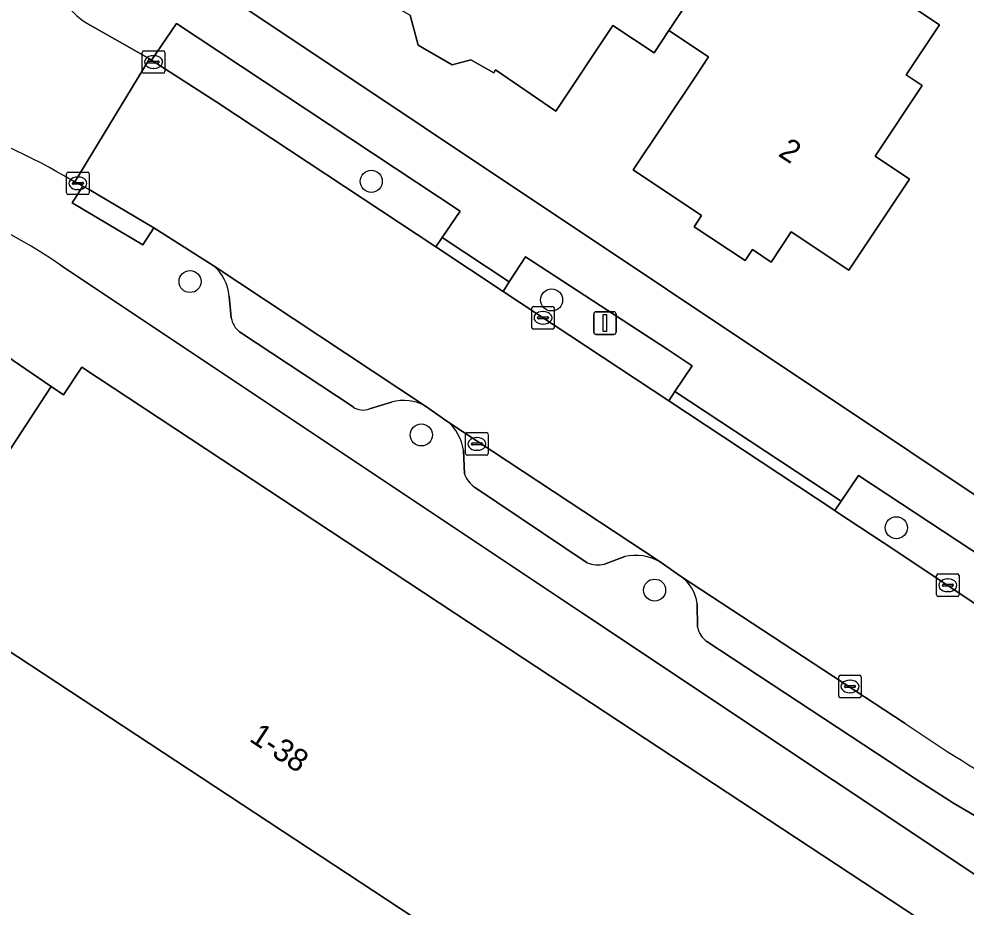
# Model space of a CAD drawing. Extents: x 161772 to 163126, y 383092 to 383917.
# Drawn here: x 162367.96 to 162409.94, y 383486.96 to 383526.35 of the extents above; entities that cross this region are included whole.
import ezdxf

# ---------------------------------------------------------------- set-up
doc = ezdxf.new("R2010")
doc.units = 0
for name, color, linetype in [('IMGEO_Boom', 7, 'Continuous'), ('IMGEO_Erf', 7, 'Continuous'), ('IMGEO_Groenvoorziening', 7, 'Continuous'), ('IMGEO_Kolk', 7, 'Continuous'), ('IMGEO_Lichtmast', 7, 'Continuous'), ('IMGEO_Pand', 7, 'Continuous'), ('IMGEO_Pand_nummerreeks', 7, 'Continuous'), ('IMGEO_Parkeervlak_open', 7, 'Continuous'), ('IMGEO_Rijbaan_lokaal_gesloten', 7, 'Continuous'), ('IMGEO_Rijbaan_lokaal_open', 7, 'Continuous'), ('IMGEO_Voetpad_open', 7, 'Continuous')]:
    doc.layers.add(name, color=color, linetype=linetype)

msp = doc.modelspace()

# ---------------------------------------------------------------- linework, layer by layer
at = {"layer": 'IMGEO_Boom'}
for centre in [(162383.578, 383519.145), (162375.545, 383514.701), (162391.571, 383513.885), (162385.797, 383507.897), (162406.85, 383503.782), (162396.136, 383501.014)]:
    msp.add_circle(centre, 0.489, dxfattribs=at)
at = {"layer": 'IMGEO_Erf'}
for points in [[(162462.704, 383536.779), (162483.744, 383554.98), (162500, 383574.599), (162526.947, 383607.122), (162543.804, 383623.317), (162548.918, 383628.126), (162539.791, 383641.093), (162527.133, 383641.683), (162527.105, 383641.456), (162500, 383642.583), (162442.25, 383644.984), (162375.184, 383528.714), (162418.191, 383500), (162425.357, 383495.215)], [(162403.897, 383529.321), (162408.758, 383526.086), (162407.282, 383523.868), (162407.993, 383523.394), (162405.908, 383520.26), (162407.433, 383519.245), (162404.746, 383515.207), (162402.195, 383516.905), (162401.305, 383515.567), (162400.476, 383516.119), (162400.148, 383515.627), (162397.885, 383517.133), (162398.22, 383517.636), (162395.189, 383519.652), (162397.959, 383523.815), (162398.523, 383524.663), (162396.772, 383525.831), (162396.111, 383524.841), (162394.289, 383526.056), (162391.754, 383522.254), (162389.089, 383524.092), (162389.009, 383523.954), (162387.994, 383524.54), (162387.16, 383524.317), (162385.651, 383525.187), (162385.295, 383526.511)], [(162415.606, 383482.867), (162415.154, 383485.181), (162392.934, 383500), (162369.796, 383515.431)]]:
    msp.add_lwpolyline(points, dxfattribs=at)
msp.add_lwpolyline([(162351.52, 383514.81), (162359.75, 383515.42), (162359.94, 383512.6), (162365.41, 383510.83), (162366.29, 383512.16), (162369.386, 383510.049), (162369.936, 383509.674), (162370.747, 383510.9), (162387.282, 383500), (162408.441, 383486.052), (162399.683, 383472.842), (162389.098, 383463.766), (162387.275, 383465.894), (162382.993, 383470.891), (162381.153, 383473.039), (162391.903, 383482.254), (162364.962, 383500), (162363.969, 383500.654), (162365.459, 383502.906), (162364.939, 383503.25), (162362.306, 383504.993), (162356.802, 383504.584), (162356.592, 383507.406), (162352.094, 383507.072)], close=True, dxfattribs=at)
msp.add_arc((162355.644, 383494.899), 24.937, 55.4234, 93.0188, dxfattribs=at)
at = {"layer": 'IMGEO_Groenvoorziening'}
for points in [[(162373.834, 383524.516), (162376.728, 383522.659), (162386.44, 383516.235), (162386.721, 383516.648), (162387.516, 383517.815), (162374.942, 383526.139)], [(162389.694, 383514.682), (162389.421, 383514.263), (162396.76, 383509.409), (162397.037, 383509.82), (162397.802, 383510.956), (162396.699, 383511.708), (162390.42, 383515.798)]]:
    msp.add_lwpolyline(points, close=True, dxfattribs=at)
for points in [[(162418.384, 383495.476), (162419.246, 383496.818), (162417.08, 383498.245), (162405.174, 383506.099), (162404.404, 383504.955)], [(162404.404, 383504.955), (162404.125, 383504.54), (162404.195, 383504.494), (162406.79, 383502.794), (162410.958, 383500), (162415.501, 383497.08)]]:
    msp.add_lwpolyline(points, dxfattribs=at)
at = {"layer": 'IMGEO_Kolk'}
for p, q in [((162373.427, 383524.01), (162373.427, 383524.862)), ((162373.502, 383524.936), (162374.354, 383524.936)), ((162373.915, 383524.716), (162373.94, 383524.716)), ((162374.428, 383524.862), (162374.428, 383524.01)), ((162373.686, 383524.43), (162373.686, 383524.442)), ((162374.124, 383524.393), (162373.726, 383524.393)), ((162373.729, 383524.479), (162374.127, 383524.479)), ((162373.938, 383524.156), (162373.913, 383524.156)), ((162374.17, 383524.442), (162374.17, 383524.43)), ((162374.354, 383523.936), (162373.502, 383523.936)), ((162370.147, 383519.556), (162370.999, 383519.556)), ((162370.072, 383518.63), (162370.072, 383519.482)), ((162370.374, 383519.099), (162370.772, 383519.099)), ((162370.56, 383519.336), (162370.585, 383519.336)), ((162371.073, 383519.482), (162371.073, 383518.63)), ((162370.331, 383519.05), (162370.331, 383519.062)), ((162370.769, 383519.013), (162370.371, 383519.013)), ((162370.583, 383518.776), (162370.558, 383518.776)), ((162370.815, 383519.062), (162370.815, 383519.05)), ((162370.999, 383518.556), (162370.147, 383518.556)), ((162390.69, 383512.667), (162390.69, 383513.519)), ((162390.765, 383513.593), (162391.617, 383513.593)), ((162391.178, 383513.373), (162391.203, 383513.373)), ((162391.691, 383513.519), (162391.691, 383512.667)), ((162390.949, 383513.087), (162390.949, 383513.099)), ((162391.387, 383513.05), (162390.989, 383513.05)), ((162390.992, 383513.136), (162391.39, 383513.136)), ((162391.201, 383512.813), (162391.176, 383512.813)), ((162391.433, 383513.099), (162391.433, 383513.087)), ((162391.617, 383512.593), (162390.765, 383512.593)), ((162387.758, 383507.072), (162387.758, 383507.924)), ((162387.833, 383507.998), (162388.685, 383507.998)), ((162388.246, 383507.778), (162388.271, 383507.778)), ((162388.759, 383507.924), (162388.759, 383507.072)), ((162388.017, 383507.492), (162388.017, 383507.504)), ((162388.455, 383507.455), (162388.057, 383507.455)), ((162388.06, 383507.541), (162388.458, 383507.541)), ((162388.501, 383507.504), (162388.501, 383507.492)), ((162388.685, 383506.998), (162387.833, 383506.998)), ((162388.269, 383507.218), (162388.244, 383507.218)), ((162408.633, 383500.804), (162408.633, 383501.656)), ((162408.708, 383501.73), (162409.56, 383501.73)), ((162409.121, 383501.51), (162409.146, 383501.51)), ((162409.634, 383501.656), (162409.634, 383500.804)), ((162408.892, 383501.224), (162408.892, 383501.236)), ((162409.33, 383501.187), (162408.932, 383501.187)), ((162408.935, 383501.273), (162409.333, 383501.273)), ((162409.376, 383501.236), (162409.376, 383501.224)), ((162409.56, 383500.73), (162408.708, 383500.73)), ((162409.144, 383500.95), (162409.119, 383500.95)), ((162404.297, 383496.315), (162404.297, 383497.167)), ((162404.372, 383497.241), (162405.224, 383497.241)), ((162404.785, 383497.021), (162404.81, 383497.021)), ((162405.298, 383497.167), (162405.298, 383496.315)), ((162404.556, 383496.735), (162404.556, 383496.747)), ((162404.994, 383496.698), (162404.596, 383496.698)), ((162404.599, 383496.784), (162404.997, 383496.784)), ((162404.808, 383496.461), (162404.783, 383496.461)), ((162405.04, 383496.747), (162405.04, 383496.735)), ((162405.224, 383496.241), (162404.372, 383496.241))]:
    msp.add_line(p, q, dxfattribs=at)
for points in [[(162373.427, 383524.01), (162373.427, 383524.862)], [(162373.502, 383524.936), (162374.354, 383524.936)], [(162374.428, 383524.862), (162374.428, 383524.01)], [(162374.354, 383523.936), (162373.502, 383523.936)], [(162370.147, 383519.556), (162370.999, 383519.556)], [(162370.072, 383518.63), (162370.072, 383519.482)], [(162371.073, 383519.482), (162371.073, 383518.63)], [(162370.999, 383518.556), (162370.147, 383518.556)], [(162390.69, 383512.667), (162390.69, 383513.519)], [(162390.765, 383513.593), (162391.617, 383513.593)], [(162391.691, 383513.519), (162391.691, 383512.667)], [(162391.617, 383512.593), (162390.765, 383512.593)], [(162387.758, 383507.072), (162387.758, 383507.924)], [(162387.833, 383507.998), (162388.685, 383507.998)], [(162388.759, 383507.924), (162388.759, 383507.072)], [(162388.685, 383506.998), (162387.833, 383506.998)], [(162408.633, 383500.804), (162408.633, 383501.656)], [(162408.708, 383501.73), (162409.56, 383501.73)], [(162409.634, 383501.656), (162409.634, 383500.804)], [(162409.56, 383500.73), (162408.708, 383500.73)], [(162404.297, 383496.315), (162404.297, 383497.167)], [(162404.372, 383497.241), (162405.224, 383497.241)], [(162405.298, 383497.167), (162405.298, 383496.315)], [(162405.224, 383496.241), (162404.372, 383496.241)]]:
    msp.add_lwpolyline(points, dxfattribs=at)
for centre, radius, start, end in [((162373.504, 383524.86), 0.0765, 91.552, 178.448), ((162373.504, 383524.86), 0.0765, 91.552, 178.448), ((162374.352, 383524.86), 0.0765, 1.552, 88.448), ((162374.352, 383524.86), 0.0765, 1.552, 88.448), ((162373.726, 383524.439), 0.0403, 85.8775, 175.7526), ((162373.723, 383524.429), 0.0366, 178.938, 274.7102), ((162374.127, 383524.436), 0.043, 264.8664, 352.4533), ((162374.131, 383524.441), 0.0386, 1.7309, 96.639), ((162373.504, 383524.012), 0.0765, 181.552, 268.448), ((162373.504, 383524.012), 0.0765, 181.552, 268.448), ((162374.352, 383524.012), 0.0765, 271.552, 358.448), ((162374.352, 383524.012), 0.0765, 271.552, 358.448), ((162370.149, 383519.48), 0.0765, 91.552, 178.448), ((162370.149, 383519.48), 0.0765, 91.552, 178.448), ((162370.997, 383519.48), 0.0765, 1.552, 88.448), ((162370.997, 383519.48), 0.0765, 1.552, 88.448), ((162370.371, 383519.059), 0.0403, 85.8775, 175.7526), ((162370.776, 383519.061), 0.0386, 1.7309, 96.639), ((162370.368, 383519.049), 0.0366, 178.938, 274.7102), ((162370.772, 383519.056), 0.043, 264.8664, 352.4533), ((162370.149, 383518.632), 0.0765, 181.552, 268.448), ((162370.149, 383518.632), 0.0765, 181.552, 268.448), ((162370.997, 383518.632), 0.0765, 271.552, 358.448), ((162370.997, 383518.632), 0.0765, 271.552, 358.448), ((162390.767, 383513.517), 0.0765, 91.552, 178.448), ((162390.767, 383513.517), 0.0765, 91.552, 178.448), ((162391.615, 383513.517), 0.0765, 1.552, 88.448), ((162391.615, 383513.517), 0.0765, 1.552, 88.448), ((162390.989, 383513.096), 0.0403, 85.8775, 175.7526), ((162390.986, 383513.086), 0.0366, 178.938, 274.7102), ((162391.39, 383513.093), 0.043, 264.8664, 352.4533), ((162391.394, 383513.098), 0.0386, 1.7309, 96.639), ((162390.767, 383512.669), 0.0765, 181.552, 268.448), ((162390.767, 383512.669), 0.0765, 181.552, 268.448), ((162391.615, 383512.669), 0.0765, 271.552, 358.448), ((162391.615, 383512.669), 0.0765, 271.552, 358.448), ((162387.835, 383507.922), 0.0765, 91.552, 178.448), ((162387.835, 383507.922), 0.0765, 91.552, 178.448), ((162388.683, 383507.922), 0.0765, 1.552, 88.448), ((162388.683, 383507.922), 0.0765, 1.552, 88.448), ((162388.057, 383507.501), 0.0403, 85.8775, 175.7526), ((162388.054, 383507.491), 0.0366, 178.938, 274.7102), ((162388.458, 383507.498), 0.043, 264.8664, 352.4533), ((162388.462, 383507.503), 0.0386, 1.7309, 96.639), ((162387.835, 383507.074), 0.0765, 181.552, 268.448), ((162387.835, 383507.074), 0.0765, 181.552, 268.448), ((162388.683, 383507.074), 0.0765, 271.552, 358.448), ((162388.683, 383507.074), 0.0765, 271.552, 358.448), ((162408.71, 383501.654), 0.0765, 91.552, 178.448), ((162408.71, 383501.654), 0.0765, 91.552, 178.448), ((162409.558, 383501.654), 0.0765, 1.552, 88.448), ((162409.558, 383501.654), 0.0765, 1.552, 88.448), ((162408.932, 383501.233), 0.0403, 85.8775, 175.7526), ((162408.929, 383501.223), 0.0366, 178.938, 274.7102), ((162409.333, 383501.23), 0.043, 264.8664, 352.4533), ((162409.337, 383501.235), 0.0386, 1.7309, 96.639), ((162408.71, 383500.806), 0.0765, 181.552, 268.448), ((162408.71, 383500.806), 0.0765, 181.552, 268.448), ((162409.558, 383500.806), 0.0765, 271.552, 358.448), ((162409.558, 383500.806), 0.0765, 271.552, 358.448), ((162404.374, 383497.165), 0.0765, 91.552, 178.448), ((162404.374, 383497.165), 0.0765, 91.552, 178.448), ((162405.222, 383497.165), 0.0765, 1.552, 88.448), ((162405.222, 383497.165), 0.0765, 1.552, 88.448), ((162404.596, 383496.744), 0.0403, 85.8775, 175.7526), ((162404.593, 383496.734), 0.0366, 178.938, 274.7102), ((162404.997, 383496.741), 0.043, 264.8664, 352.4533), ((162405.001, 383496.746), 0.0386, 1.7309, 96.639), ((162404.374, 383496.317), 0.0765, 181.552, 268.448), ((162404.374, 383496.317), 0.0765, 181.552, 268.448), ((162405.222, 383496.317), 0.0765, 271.552, 358.448), ((162405.222, 383496.317), 0.0765, 271.552, 358.448)]:
    msp.add_arc(centre, radius, start, end, dxfattribs=at)
for centre, major_axis, ratio, start_param, end_param in [((162373.914, 383524.436), (-0.387, 0.002), 0.722429, 4.712389, 7.853982), ((162373.939, 383524.436), (-0.39, 0.002), 0.717154, 1.570796, 4.712389), ((162370.559, 383519.056), (-0.387, 0.002), 0.722429, 4.712389, 7.853982), ((162370.584, 383519.056), (-0.39, 0.002), 0.717154, 1.570796, 4.712389), ((162391.177, 383513.093), (-0.387, 0.002), 0.722429, 4.712389, 7.853982), ((162391.202, 383513.093), (-0.39, 0.002), 0.717154, 1.570796, 4.712389), ((162388.245, 383507.498), (-0.387, 0.002), 0.722429, 4.712389, 7.853982), ((162388.27, 383507.498), (-0.39, 0.002), 0.717154, 1.570796, 4.712389), ((162409.12, 383501.23), (-0.387, 0.002), 0.722429, 4.712389, 7.853982), ((162409.145, 383501.23), (-0.39, 0.002), 0.717154, 1.570796, 4.712389), ((162404.784, 383496.741), (-0.387, 0.002), 0.722429, 4.712389, 7.853982), ((162404.809, 383496.741), (-0.39, 0.002), 0.717154, 1.570796, 4.712389)]:
    msp.add_ellipse(centre, major_axis=major_axis, ratio=ratio, start_param=start_param, end_param=end_param, dxfattribs=at)
at = {"layer": 'IMGEO_Lichtmast'}
for p, q in [((162393.437, 383512.459), (162393.437, 383513.259)), ((162393.437, 383513.259), (162393.437, 383512.459)), ((162393.537, 383513.359), (162394.327, 383513.359)), ((162394.327, 383513.359), (162393.537, 383513.359)), ((162394.427, 383513.259), (162394.427, 383512.459)), ((162394.427, 383512.459), (162394.427, 383513.259)), ((162394.327, 383512.359), (162393.537, 383512.359)), ((162393.537, 383512.359), (162394.327, 383512.359))]:
    msp.add_line(p, q, dxfattribs=at)
msp.add_lwpolyline([(162393.857, 383513.234), (162394.007, 383513.234), (162394.007, 383512.484), (162393.857, 383512.484), (162393.857, 383513.234)], dxfattribs=at)
for centre, start, end in [((162393.537, 383513.259), 90, 180), ((162393.537, 383513.259), 90, 180), ((162394.327, 383513.259), 0, 90), ((162394.327, 383513.259), 360, 90), ((162393.537, 383512.459), 180, 270), ((162393.537, 383512.459), 180, 270), ((162394.327, 383512.459), 270, 0), ((162394.327, 383512.459), 270, 0)]:
    msp.add_arc(centre, 0.1, start, end, dxfattribs=at)
at = {"layer": 'IMGEO_Pand'}
for points in [[(162399.551, 383529.998), (162400.202, 383530.976), (162393.215, 383535.465), (162391.317, 383532.512), (162389.13, 383533.918), (162389.026, 383533.768), (162387.838, 383534.453), (162386.648, 383534.452), (162385.666, 383532.751), (162385.959, 383531.659), (162387.161, 383530.966), (162384.511, 383526.964), (162385.295, 383526.511), (162385.651, 383525.187), (162387.16, 383524.317), (162387.994, 383524.54), (162389.009, 383523.954), (162389.089, 383524.092), (162391.754, 383522.254), (162394.289, 383526.056), (162396.111, 383524.841), (162396.772, 383525.831)], [(162399.551, 383529.998), (162396.772, 383525.831), (162398.523, 383524.663), (162397.959, 383523.815), (162395.189, 383519.652), (162398.22, 383517.636), (162397.885, 383517.133), (162400.148, 383515.627), (162400.476, 383516.119), (162401.305, 383515.567), (162402.195, 383516.905), (162404.746, 383515.207), (162407.433, 383519.245), (162405.908, 383520.26), (162407.993, 383523.394), (162407.282, 383523.868), (162408.758, 383526.086), (162403.897, 383529.321), (162402.399, 383527.07), (162400.823, 383528.119), (162401.299, 383528.834)], [(162364.939, 383503.25), (162369.386, 383510.049), (162366.29, 383512.16), (162365.41, 383510.83), (162359.94, 383512.6), (162359.75, 383515.42), (162351.52, 383514.81), (162352.094, 383507.072), (162356.592, 383507.406), (162356.802, 383504.584), (162362.306, 383504.993)], [(162364.939, 383503.25), (162365.459, 383502.906), (162363.969, 383500.654), (162364.962, 383500), (162391.903, 383482.254), (162381.153, 383473.039), (162382.993, 383470.891), (162387.275, 383465.894), (162389.098, 383463.766), (162399.683, 383472.842), (162408.441, 383486.052), (162387.282, 383500), (162370.747, 383510.9), (162369.936, 383509.674), (162369.386, 383510.049)]]:
    msp.add_lwpolyline(points, close=True, dxfattribs=at)
at = {"layer": 'IMGEO_Parkeervlak_open'}
for points in [[(162385.982, 383509.168), (162376.564, 383515.408)], [(162377.276, 383514.059), (162377.368, 383513.091)], [(162377.742, 383512.469), (162382.771, 383509.14)], [(162383.497, 383509.057), (162384.479, 383509.356)], [(162396.376, 383502.271), (162386.933, 383508.51)], [(162387.662, 383507.225), (162387.706, 383506.17)], [(162388.148, 383505.586), (162393.153, 383502.222)], [(162393.908, 383502.163), (162394.812, 383502.507)], [(162407.244, 383495.103), (162397.286, 383501.636)], [(162398.024, 383500.411), (162398.038, 383499.365)], [(162398.456, 383498.732), (162407.701, 383492.642), (162409.387, 383491.566), (162410.568, 383490.866)]]:
    msp.add_lwpolyline(points, dxfattribs=at)
for centre, radius, start, end in [((162375.378, 383513.919), 1.904, 4.205, 51.445), ((162378.377, 383513.274), 1.025, 190.2892, 231.7467), ((162385.009, 383507.493), 1.937, 59.8483, 105.8923), ((162383.211, 383509.773), 0.771, 235.1982, 291.7578), ((162385.674, 383506.946), 2.008, 7.9775, 51.1563), ((162388.947, 383506.65), 1.33, 201.1405, 233.0999), ((162395.285, 383500.338), 2.22, 60.5459, 102.2922), ((162393.625, 383503.408), 1.277, 248.2784, 282.7849), ((162396.278, 383500.194), 1.759, 7.0866, 55.047), ((162399.129, 383499.631), 1.123, 193.6931, 233.1842), ((162441.367, 383544.326), 59.894, 235.26876, 240.96925)]:
    msp.add_arc(centre, radius, start, end, dxfattribs=at)
at = {"layer": 'IMGEO_Rijbaan_lokaal_gesloten'}
for points in [[(162396.76, 383509.409), (162389.421, 383514.263), (162386.44, 383516.235), (162376.728, 383522.659), (162373.834, 383524.516), (162373.747, 383524.572), (162370.441, 383519.129), (162370.793, 383518.936), (162371.077, 383518.78), (162373.944, 383517.081), (162376.564, 383515.408), (162385.982, 383509.168), (162386.933, 383508.51), (162396.376, 383502.271), (162397.286, 383501.636), (162407.244, 383495.103)], [(162415.501, 383497.08), (162410.958, 383500), (162406.79, 383502.794), (162404.195, 383504.494), (162404.125, 383504.54), (162396.76, 383509.409)]]:
    msp.add_lwpolyline(points, dxfattribs=at)
msp.add_arc((162441.367, 383544.326), 59.894, 235.26876, 240.96925, dxfattribs=at)
at = {"layer": 'IMGEO_Rijbaan_lokaal_open'}
msp.add_lwpolyline([(162369.997, 383519.372), (162370.441, 383519.129), (162373.747, 383524.572), (162371.119, 383526.076)], dxfattribs=at)
for centre, radius, start, end in [((162372.859, 383529.185), 3.563, 151.0941, 240.7684), ((162356.098, 383495.402), 27.708, 59.8918, 86.7549)]:
    msp.add_arc(centre, radius, start, end, dxfattribs=at)
at = {"layer": 'IMGEO_Voetpad_open'}
for points in [[(162418.191, 383500), (162375.184, 383528.714), (162370.031, 383531.42), (162369.74, 383530.907)], [(162371.119, 383526.076), (162373.747, 383524.572), (162373.834, 383524.516), (162374.942, 383526.139), (162387.516, 383517.815), (162386.721, 383516.648), (162389.694, 383514.682), (162390.42, 383515.798), (162396.699, 383511.708), (162397.802, 383510.956), (162397.037, 383509.82), (162404.404, 383504.955), (162405.174, 383506.099), (162417.08, 383498.245), (162419.246, 383496.818), (162418.384, 383495.476), (162418.538, 383495.404), (162423.223, 383493.366)], [(162376.564, 383515.408), (162373.944, 383517.081), (162373.448, 383516.33), (162370.313, 383518.185), (162370.793, 383518.936), (162370.441, 383519.129), (162369.997, 383519.372)], [(162369.796, 383515.431), (162392.934, 383500), (162415.154, 383485.181), (162415.606, 383482.867), (162418.449, 383481.247)], [(162377.368, 383513.091), (162377.276, 383514.059)], [(162382.771, 383509.14), (162377.742, 383512.469)], [(162384.479, 383509.356), (162383.497, 383509.057)], [(162386.933, 383508.51), (162385.982, 383509.168)], [(162387.706, 383506.17), (162387.662, 383507.225)], [(162393.153, 383502.222), (162388.148, 383505.586)], [(162394.812, 383502.507), (162393.908, 383502.163)], [(162397.286, 383501.636), (162396.376, 383502.271)], [(162398.038, 383499.365), (162398.024, 383500.411)], [(162410.568, 383490.866), (162409.387, 383491.566), (162407.701, 383492.642), (162398.456, 383498.732)]]:
    msp.add_lwpolyline(points, dxfattribs=at)
for points in [[(162373.448, 383516.33), (162373.944, 383517.081), (162371.077, 383518.78), (162370.793, 383518.936), (162370.313, 383518.185)], [(162386.721, 383516.648), (162386.44, 383516.235), (162389.421, 383514.263), (162389.694, 383514.682)], [(162397.037, 383509.82), (162396.76, 383509.409), (162404.125, 383504.54), (162404.404, 383504.955)]]:
    msp.add_lwpolyline(points, close=True, dxfattribs=at)
for centre, radius, start, end in [((162372.859, 383529.185), 3.563, 151.0941, 240.7684), ((162356.098, 383495.402), 27.708, 59.8918, 86.7549), ((162355.644, 383494.899), 24.937, 55.4234, 93.0188), ((162375.378, 383513.919), 1.904, 4.205, 51.445), ((162378.377, 383513.274), 1.025, 190.2892, 231.7467), ((162385.009, 383507.493), 1.937, 59.8483, 105.8923), ((162383.211, 383509.773), 0.771, 235.1982, 291.7578), ((162385.674, 383506.946), 2.008, 7.9775, 51.1563), ((162388.947, 383506.65), 1.33, 201.1405, 233.0999), ((162395.285, 383500.338), 2.22, 60.5459, 102.2922), ((162393.625, 383503.408), 1.277, 248.2784, 282.7849), ((162396.278, 383500.194), 1.759, 7.0866, 55.047), ((162399.129, 383499.631), 1.123, 193.6931, 233.1842)]:
    msp.add_arc(centre, radius, start, end, dxfattribs=at)

# ---------------------------------------------------------------- texts
at = {"layer": 'IMGEO_Pand_nummerreeks'}
for s, rotation, p in [('2', 326.7687, (162401.572, 383520.299)), ('1-38', 326.6273, (162378.123, 383494.348))]:
    msp.add_text(s, height=1, rotation=rotation, dxfattribs=at).set_placement(p)

doc.saveas('drawing.dxf')
